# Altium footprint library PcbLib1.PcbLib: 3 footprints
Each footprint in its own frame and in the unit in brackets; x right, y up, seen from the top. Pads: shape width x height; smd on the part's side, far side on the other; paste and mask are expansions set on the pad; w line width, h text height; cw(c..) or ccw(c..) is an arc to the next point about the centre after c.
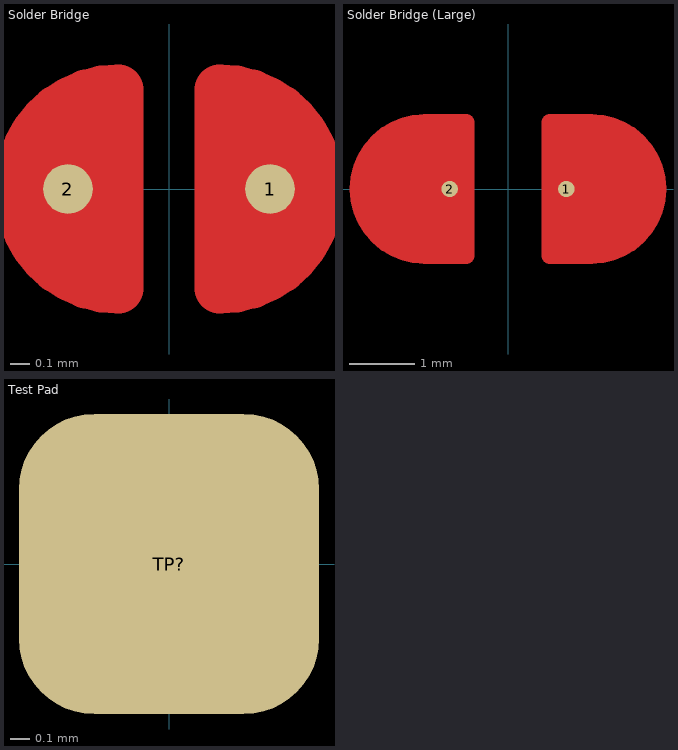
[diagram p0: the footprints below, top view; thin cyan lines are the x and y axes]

## Solder Bridge [mm]
pads (2):
  round 0.25 smd mask+0: 1(0.508,0) 2(-0.508,0)
Top Layer:
  region: 0.254,0.5 0.449,0.456 0.754,0.181 0.754,-0.164 0.519,-0.399 0.449,-0.469 0.254,-0.5
  region: -0.254,-0.5 -0.449,-0.456 -0.754,-0.181 -0.754,0.164 -0.519,0.399 -0.449,0.469 -0.254,0.5
  lines w0.254: -0.254,-0.5 cw(c-0.254,0) -0.254,0.5 -0.254,-0.5 ; 0.254,-0.5 ccw(c0.254,0) 0.254,0.5 0.254,-0.5
Top Solder:
  circle w0.8: c-0.254,0 r0.25
  circle w0.8: c0.254,0 r0.25
  lines w0.254: -0.254,-0.52 0.254,-0.52 ; -0.254,0.52 0.254,0.52

## Solder Bridge (Large) [mm]
pads (2):
  round 0.25 smd mask+0: 1(0.889,0) 2(-0.889,0)
Top Layer:
  region: -0.635,-1.016 -1.651,-1.016 -2.286,-0.381 -2.286,0.381 -1.651,1.016 -0.635,1.016
  region: 0.635,1.016 1.651,1.016 2.286,0.381 2.286,-0.381 1.651,-1.016 0.635,-1.016
  lines w0.254: -0.635,-1.016 -1.27,-1.016 cw(c-1.27,0) -2.286,0 cw(c-1.27,0) -1.27,1.016 -0.635,1.016 ; -0.635,-1 -0.635,1 ; 0.635,-1.016 1.27,-1.016 ccw(c1.27,0) 2.286,0 ccw(c1.27,0) 1.27,1.016 0.635,1.016 ; 0.635,-1 0.635,1
Top Solder:
  circle w2: c-1.27,0 r0.25
  circle w2: c1.27,0 r0.25
  lines w0.254: 0,-1.016 0,1.016
  lines w1: -1.263,-0.707 -0.599,-0.707 -0.545,-0.762 ; -1.25,-0.762 1.25,-0.762 ; -1.25,0.762 1.25,0.762 ; 0.673,-0.762 0.728,-0.707 1.392,-0.707

## Test Pad [mil]
pads (1):
  rrect50% 60x60 smd: TP?(0,0)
